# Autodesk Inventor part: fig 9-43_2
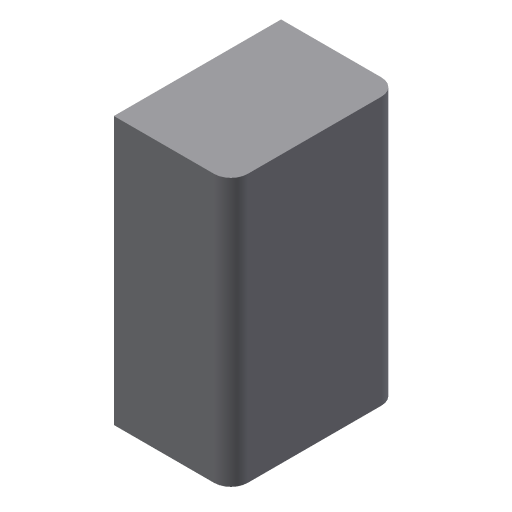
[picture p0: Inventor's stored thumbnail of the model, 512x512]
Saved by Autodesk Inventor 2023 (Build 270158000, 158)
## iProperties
Created: 2013-03
Part Number: fig 9-43_2
Material: Generic
Document SubType Name: Modeling
Designer: CADCIM
Density: 1 g/cm^3
Appearance: Default
Author: CADCIM
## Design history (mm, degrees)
sketch "Sketch1"
  geometry: L1 (-2.508, 1.862)-(2.492, 1.862); L2 (2.492, 1.862)-(2.492, -6.138); L3 (2.492, -6.138)-(-2.508, -6.138); L4 (-2.508, -6.138)-(-2.508, 1.862); 1 further point
  constraints: 8 end point, 2 parallel, 1 horizontal, 1 perpendicular
  dimensions: "d0" = 5 distance of L1.start L1.end; "d2" = 8 distance of L1.end L2.end
extrude "Extrusion1" new body sketch "Sketch1" distance "d3" = 3.5; taper "d4" = 0 deg
fillet "Fillet1" dims "d5" = 0.5
fillet "Fillet2" dims "d6" = 0.5
body "Solid1"
